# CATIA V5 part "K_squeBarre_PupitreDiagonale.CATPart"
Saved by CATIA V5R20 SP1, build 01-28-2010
Part number: squelette_barre_pupitre_diagonale
Publications: "Point.1", "Point.2", "Plan.1", "Droite.1", "Droite.2", "Droite.3"
Bounding box of the stored display mesh (mm): x 0 to 20, y 0 to 0, z 0 to 141.421
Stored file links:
  G:\Khaled_CFAO_2011\ST2M\ST2M_GR2\gcausse\Khaled\CAD_ThinkMotion\K_squeBarre_PupitreDiagonale.CATPart
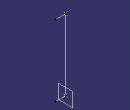
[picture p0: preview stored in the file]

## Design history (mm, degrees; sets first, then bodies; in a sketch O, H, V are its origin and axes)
Set1
  Point1: (0, 0, 0)
  Point2: (0, 0, 141.4214 {= 200mm*sqrt(2)/2})
  Plane1: type Offset, RefPlane yz-plane, Offset 0
  Line1: type PtPt, FirstPoint Point2, SecondPoint Point1
  Line2: type PtDir, RefPoint Point2, Direction Plane1, Start 0, End 20
  Line3: type PtDir, RefPoint Point1, Direction Plane1, Start 0, End 20
Body1 (main body)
